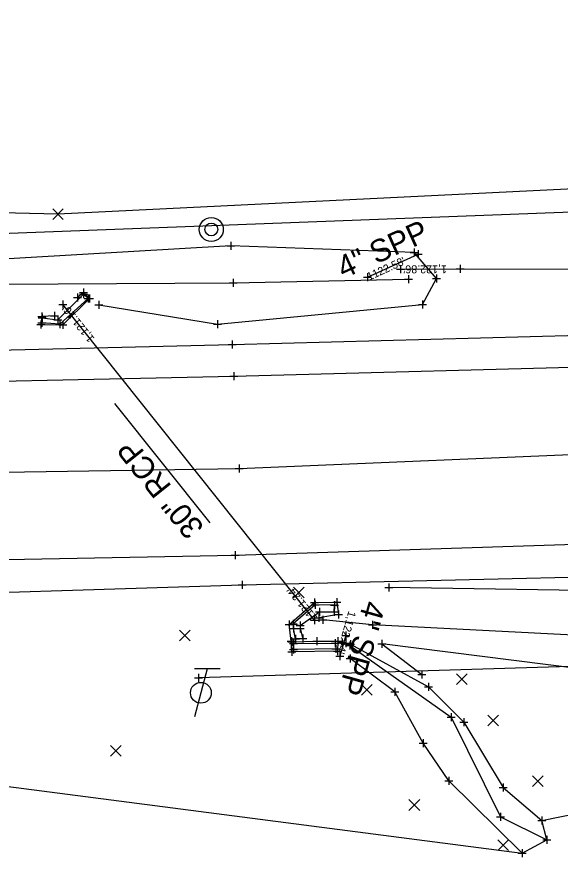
# Model space of a CAD drawing. Extents: x 2402028 to 2407435, y 498611 to 499105.
# Drawn here: x 2404008.8 to 2404076.7, y 498644.5 to 498749.5 of the extents above; entities that cross this region are included whole.
import ezdxf

# ---------------------------------------------------------------- set-up
doc = ezdxf.new("R2010")
doc.units = 0
for name, color, linetype in [('Default', 7, 'Continuous'), ('DR_X_Ditch', 7, 'Continuous'), ('DR_X_Headwall', 7, 'Continuous'), ('DR_X_Storm_Sewer', 7, 'Continuous'), ('DR_X_Text', 7, 'Continuous'), ('PV_X_COP', 7, 'Continuous'), ('PV_X_EOP', 7, 'Continuous'), ('PV_X_Shoulder', 7, 'Continuous'), ('RD_X_Wall', 7, 'Continuous'), ('RW_X_CL_1000_Distances', 7, 'Continuous'), ('RW_X_CL_100_Stations', 7, 'Continuous'), ('RW_X_CL_500_Bearings', 7, 'Continuous'), ('RW_X_CL_500_Distances', 7, 'Continuous'), ('RW_X_CL_500_Stations', 7, 'Continuous'), ('SC_Scratch1', 7, 'Continuous'), ('SV_X_Break_Lines', 7, 'Continuous'), ('SV_X_Terrain_Boundary', 7, 'Continuous'), ('UT_X_Telecom', 7, 'Continuous')]:
    doc.layers.add(name, color=color, linetype=linetype)

msp = doc.modelspace()

# ---------------------------------------------------------------- linework, layer by layer
at = {"layer": 'Default'}
for p, q in [((2404056.73, 498717.91), (2404056.73, 498717.91)), ((2404052.58, 498716.95), (2404052.58, 498716.95)), ((2404049.87, 498672.15), (2404049.87, 498672.15))]:
    msp.add_line(p, q, dxfattribs=at)
at = {"layer": 'DR_X_Ditch'}
for points in [[(2403115.12, 498695.09), (2403139.28, 498697.03), (2403188.69, 498698.47), (2403237.26, 498698.52), (2403287.58, 498700.04), (2403338.31, 498701.02), (2403388.05, 498703.88), (2403439.2, 498702.19), (2403487.16, 498703.92), (2403540.55, 498705.7), (2403586.78, 498706.71), (2403636.91, 498706.23), (2403686.46, 498707.34), (2403736.22, 498708.05), (2403785.8, 498709.01), (2403836.25, 498710.7), (2403885.81, 498712.33), (2403935.71, 498713.55), (2403984.74, 498715.92), (2404035.79, 498716.24), (2404057.73, 498716.67)], [(2404533.24, 498683.6), (2404485.13, 498682.32), (2404436.39, 498681.96), (2404386.54, 498679.04), (2404337.17, 498678.98), (2404287.56, 498677.96), (2404236.98, 498675.49), (2404187.96, 498674.52), (2404135.48, 498673.31), (2404086.4, 498671.8), (2404053.2, 498673.48), (2404047.02, 498674.14)], [(2404049.43, 498671.29), (2404049.9, 498671.22), (2404050.39, 498670.91), (2404063.05, 498661.97), (2404069.21, 498649.49), (2404075.01, 498646.62)]]:
    msp.add_lwpolyline(points, dxfattribs=at)
at = {"layer": 'DR_X_Headwall'}
msp.add_lwpolyline([(2404048.44, 498675.13), (2404048.49, 498675.97), (2404046.06, 498676), (2404043.3, 498673.64), (2404044.17, 498673.42), (2404046.58, 498675.13)], close=True, dxfattribs=at)
at = {"layer": 'DR_X_Storm_Sewer'}
for p, q in [((2404052.58, 498716.95), (2404058.92, 498719.82)), ((2404165.84, 498717.88), (2404056.73, 498717.91)), ((2404045.99, 498674.09), (2404014.53, 498713.5)), ((2404049.87, 498672.15), (2404049.14, 498669.58))]:
    msp.add_line(p, q, dxfattribs=at)
at = {"layer": 'DR_X_Text'}
msp.add_line((2404020.99, 498701.16), (2404032.89, 498686.25), dxfattribs=at)
at = {"layer": 'PV_X_COP'}
msp.add_lwpolyline([(2403985.57, 498692.23), (2404036.54, 498693.02), (2404085.82, 498695.1), (2404135.38, 498696.42), (2404186.49, 498697.31), (2404235.26, 498698.66), (2404284.95, 498699.47), (2404334.96, 498700.99), (2404383.89, 498702.2), (2404434.73, 498703.18), (2404484.39, 498704.35), (2404533.55, 498705.6)], dxfattribs=at)
at = {"layer": 'PV_X_EOP'}
for points in [[(2403338.61, 498686.54), (2403387.34, 498688.53), (2403437.74, 498689.31), (2403487.06, 498690.99), (2403539.21, 498692.01), (2403587.62, 498693.45), (2403637.16, 498694.45), (2403686.98, 498695.6), (2403736.54, 498696.76), (2403786.79, 498698.23), (2403836.48, 498699.49), (2403886.02, 498700.75), (2403935.9, 498702.14), (2403985.32, 498703.46), (2404035.9, 498704.57), (2404085.81, 498705.89), (2404135.13, 498707.56), (2404185.41, 498708.59), (2404200.68, 498708.71)], [(2403985.56, 498681.24), (2404036.04, 498682.2), (2404086.24, 498683.82), (2404136.5, 498684.82), (2404187.36, 498686.15), (2404235.32, 498687.11), (2404285.36, 498688.37), (2404336.4, 498689.7), (2404384.93, 498690.9), (2404435.67, 498692.09), (2404485.01, 498693.22), (2404533.25, 498694.59)]]:
    msp.add_lwpolyline(points, dxfattribs=at)
at = {"layer": 'PV_X_Shoulder'}
for p, q in [((2404035.7, 498708.5), (2404085.38, 498709.86)), ((2403985.28, 498707.32), (2404035.7, 498708.5))]:
    msp.add_line(p, q, dxfattribs=at)
msp.add_lwpolyline([(2403986.56, 498676.91), (2404036.95, 498678.51), (2404086.64, 498679.64), (2404136.45, 498680.88), (2404187.63, 498682.62), (2404236.08, 498683.33), (2404286.33, 498684.49), (2404336.81, 498686.17), (2404385.43, 498687.48), (2404436.29, 498688.5), (2404485.75, 498689.82), (2404533.69, 498691.17)], dxfattribs=at)
at = {"layer": 'RD_X_Wall'}
for points in [[(2404017.11, 498714.8), (2404017.7, 498714.26), (2404014.15, 498711.05), (2404011.91, 498711.23), (2404011.93, 498711.84), (2404013.9, 498711.62)], [(2404044.52, 498671.77), (2404043.6, 498671.73), (2404043.35, 498673.05), (2404044.16, 498673.04)], [(2404043.34, 498670.42), (2404043.34, 498671.16), (2404048.56, 498671.21), (2404048.64, 498670.51)]]:
    msp.add_lwpolyline(points, close=True, dxfattribs=at)
at = {"layer": 'RW_X_CL_1000_Distances'}
for p, q in [((2404032.58, 498668.01), (2404030.97, 498662.01)), ((2404034.18, 498668.01), (2404030.98, 498668.01))]:
    msp.add_line(p, q, dxfattribs=at)
msp.add_circle((2404031.78, 498665.01), 1.3, dxfattribs=at)
at = {"layer": 'RW_X_CL_100_Stations'}
for radius in [1.5, 0.8]:
    msp.add_circle((2404033.08, 498722.89), radius, dxfattribs=at)
at = {"layer": 'RW_X_CL_500_Bearings'}
for p, q in [((2404035, 498720.85), (2404036, 498720.85)), ((2404035.5, 498721.35), (2404035.5, 498720.35)), ((2404035.5, 498720.85), (2404035.5, 498720.85)), ((2404058.41, 498720.52), (2404058.41, 498719.52)), ((2404057.91, 498720.02), (2404058.91, 498720.02)), ((2404058.41, 498720.02), (2404058.41, 498720.02)), ((2404035.29, 498716.24), (2404036.29, 498716.24)), ((2404035.79, 498716.74), (2404035.79, 498715.74)), ((2404035.79, 498716.24), (2404035.79, 498716.24)), ((2404057.23, 498716.67), (2404058.23, 498716.67)), ((2404057.73, 498717.17), (2404057.73, 498716.17)), ((2404057.73, 498716.67), (2404057.73, 498716.67)), ((2404060.73, 498716.75), (2404061.73, 498716.75)), ((2404061.23, 498717.25), (2404061.23, 498716.25)), ((2404061.23, 498716.75), (2404061.23, 498716.75)), ((2404017.11, 498715.3), (2404017.11, 498714.3)), ((2404017.12, 498715.5), (2404017.12, 498714.5)), ((2404015.85, 498714.41), (2404016.85, 498714.41)), ((2404016.35, 498714.91), (2404016.35, 498713.91)), ((2404016.35, 498714.41), (2404016.35, 498714.41)), ((2404016.61, 498714.8), (2404017.61, 498714.8)), ((2404016.62, 498715), (2404017.62, 498715)), ((2404017.11, 498714.8), (2404017.11, 498714.8)), ((2404017.12, 498715), (2404017.12, 498715)), ((2404017.2, 498714.26), (2404018.2, 498714.26)), ((2404017.36, 498714.25), (2404018.36, 498714.25)), ((2404017.7, 498714.76), (2404017.7, 498713.76)), ((2404017.7, 498714.26), (2404017.7, 498714.26)), ((2404017.86, 498714.75), (2404017.86, 498713.75)), ((2404017.86, 498714.25), (2404017.86, 498714.25)), ((2404018.54, 498713.49), (2404019.54, 498713.49)), ((2404019.04, 498713.99), (2404019.04, 498712.99)), ((2404019.04, 498713.49), (2404019.04, 498713.49)), ((2404058.98, 498713.51), (2404059.98, 498713.51)), ((2404059.48, 498714.01), (2404059.48, 498713.01)), ((2404059.48, 498713.51), (2404059.48, 498713.51)), ((2404011.41, 498712.01), (2404012.41, 498712.01)), ((2404011.91, 498712.51), (2404011.91, 498711.51)), ((2404011.91, 498712.01), (2404011.91, 498712.01)), ((2404011.93, 498712.34), (2404011.93, 498711.34)), ((2404012.98, 498712.1), (2404013.98, 498712.1)), ((2404013.48, 498712.6), (2404013.48, 498711.6)), ((2404013.48, 498712.1), (2404013.48, 498712.1)), ((2404013.9, 498712.12), (2404013.9, 498711.12)), ((2404011.27, 498711.01), (2404012.27, 498711.01)), ((2404011.41, 498711.23), (2404012.41, 498711.23)), ((2404011.43, 498711.84), (2404012.43, 498711.84)), ((2404011.77, 498711.51), (2404011.77, 498710.51)), ((2404011.77, 498711.01), (2404011.77, 498711.01)), ((2404011.91, 498711.73), (2404011.91, 498710.73)), ((2404011.91, 498711.23), (2404011.91, 498711.23)), ((2404011.93, 498711.84), (2404011.93, 498711.84)), ((2404013.4, 498711.62), (2404014.4, 498711.62)), ((2404013.65, 498711.05), (2404014.65, 498711.05)), ((2404013.9, 498711.62), (2404013.9, 498711.62)), ((2404014.03, 498710.96), (2404015.03, 498710.96)), ((2404014.15, 498711.55), (2404014.15, 498710.55)), ((2404014.15, 498711.05), (2404014.15, 498711.05)), ((2404014.53, 498711.46), (2404014.53, 498710.46)), ((2404014.53, 498710.96), (2404014.53, 498710.96)), ((2404033.34, 498711.06), (2404034.34, 498711.06)), ((2404033.84, 498711.56), (2404033.84, 498710.56)), ((2404033.84, 498711.06), (2404033.84, 498711.06)), ((2404035.7, 498709), (2404035.7, 498708)), ((2404035.2, 498708.5), (2404036.2, 498708.5)), ((2404035.7, 498708.5), (2404035.7, 498708.5)), ((2404035.9, 498705.07), (2404035.9, 498704.07)), ((2404035.4, 498704.57), (2404036.4, 498704.57)), ((2404035.9, 498704.57), (2404035.9, 498704.57)), ((2404036.54, 498693.52), (2404036.54, 498692.52)), ((2404036.04, 498693.02), (2404037.04, 498693.02)), ((2404036.54, 498693.02), (2404036.54, 498693.02)), ((2404036.04, 498682.7), (2404036.04, 498681.7)), ((2404035.54, 498682.2), (2404036.54, 498682.2)), ((2404036.04, 498682.2), (2404036.04, 498682.2)), ((2404036.45, 498678.51), (2404037.45, 498678.51)), ((2404036.95, 498679.01), (2404036.95, 498678.01)), ((2404036.95, 498678.51), (2404036.95, 498678.51)), ((2404055.25, 498678.64), (2404055.25, 498677.64)), ((2404054.75, 498678.14), (2404055.75, 498678.14)), ((2404055.25, 498678.14), (2404055.25, 498678.14)), ((2404045.97, 498676.77), (2404045.97, 498675.77)), ((2404046.06, 498676.5), (2404046.06, 498675.5)), ((2404048.26, 498676.34), (2404049.26, 498676.34)), ((2404048.49, 498676.47), (2404048.49, 498675.47)), ((2404048.76, 498676.84), (2404048.76, 498675.84)), ((2404048.76, 498676.34), (2404048.76, 498676.34)), ((2404045.47, 498676.27), (2404046.47, 498676.27)), ((2404045.56, 498676), (2404046.56, 498676)), ((2404045.97, 498676.27), (2404045.97, 498676.27)), ((2404046.06, 498676), (2404046.06, 498676)), ((2404046.58, 498675.63), (2404046.58, 498674.63)), ((2404047.99, 498675.97), (2404048.99, 498675.97)), ((2404048.44, 498675.63), (2404048.44, 498674.63)), ((2404048.49, 498675.97), (2404048.49, 498675.97)), ((2404048.97, 498675.28), (2404048.97, 498674.28)), ((2404046.01, 498674.37), (2404047.01, 498674.37)), ((2404046.08, 498675.13), (2404047.08, 498675.13)), ((2404046.51, 498674.87), (2404046.51, 498673.87)), ((2404046.51, 498674.37), (2404046.51, 498674.37)), ((2404046.58, 498675.13), (2404046.58, 498675.13)), ((2404047.02, 498674.64), (2404047.02, 498673.64)), ((2404047.94, 498675.13), (2404048.94, 498675.13)), ((2404048.44, 498675.13), (2404048.44, 498675.13)), ((2404048.47, 498674.78), (2404049.47, 498674.78)), ((2404048.97, 498674.78), (2404048.97, 498674.78)), ((2404042.29, 498673.54), (2404043.29, 498673.54)), ((2404042.79, 498674.04), (2404042.79, 498673.04)), ((2404042.79, 498673.54), (2404042.79, 498673.54)), ((2404042.8, 498673.64), (2404043.8, 498673.64)), ((2404043.3, 498674.14), (2404043.3, 498673.14)), ((2404043.3, 498673.64), (2404043.3, 498673.64)), ((2404043.35, 498673.55), (2404043.35, 498672.55)), ((2404043.67, 498673.42), (2404044.67, 498673.42)), ((2404044.16, 498673.54), (2404044.16, 498672.54)), ((2404044.17, 498673.92), (2404044.17, 498672.92)), ((2404044.17, 498673.42), (2404044.17, 498673.42)), ((2404046.52, 498674.14), (2404047.52, 498674.14)), ((2404047.02, 498674.14), (2404047.02, 498674.14)), ((2404052.7, 498673.48), (2404053.7, 498673.48)), ((2404053.2, 498673.98), (2404053.2, 498672.98)), ((2404053.2, 498673.48), (2404053.2, 498673.48)), ((2404042.85, 498673.05), (2404043.85, 498673.05)), ((2404043.35, 498673.05), (2404043.35, 498673.05)), ((2404043.6, 498672.23), (2404043.6, 498671.23)), ((2404043.66, 498673.04), (2404044.66, 498673.04)), ((2404044.16, 498673.04), (2404044.16, 498673.04)), ((2404044.52, 498672.27), (2404044.52, 498671.27)), ((2404042.57, 498671.45), (2404043.57, 498671.45)), ((2404042.64, 498671.38), (2404043.64, 498671.38)), ((2404042.84, 498671.16), (2404043.84, 498671.16)), ((2404043.07, 498671.95), (2404043.07, 498670.95)), ((2404043.07, 498671.45), (2404043.07, 498671.45)), ((2404043.1, 498671.73), (2404044.1, 498671.73)), ((2404043.14, 498671.88), (2404043.14, 498670.88)), ((2404043.14, 498671.38), (2404043.14, 498671.38)), ((2404043.34, 498671.66), (2404043.34, 498670.66)), ((2404043.34, 498671.16), (2404043.34, 498671.16)), ((2404043.6, 498671.73), (2404043.6, 498671.73)), ((2404044.02, 498671.77), (2404045.02, 498671.77)), ((2404044.52, 498671.77), (2404044.52, 498671.77)), ((2404045.77, 498671.46), (2404046.77, 498671.46)), ((2404046.27, 498671.96), (2404046.27, 498670.96)), ((2404046.27, 498671.46), (2404046.27, 498671.46)), ((2404048.06, 498671.21), (2404049.06, 498671.21)), ((2404048.38, 498671.47), (2404049.38, 498671.47)), ((2404048.56, 498671.71), (2404048.56, 498670.71)), ((2404048.56, 498671.21), (2404048.56, 498671.21)), ((2404048.88, 498671.97), (2404048.88, 498670.97)), ((2404048.88, 498671.47), (2404048.88, 498671.47)), ((2404048.93, 498671.29), (2404049.93, 498671.29)), ((2404049.4, 498671.22), (2404050.4, 498671.22)), ((2404049.43, 498671.79), (2404049.43, 498670.79)), ((2404049.43, 498671.29), (2404049.43, 498671.29)), ((2404049.9, 498671.72), (2404049.9, 498670.72)), ((2404049.9, 498671.22), (2404049.9, 498671.22)), ((2404049.96, 498671.09), (2404050.96, 498671.09)), ((2404050.39, 498671.41), (2404050.39, 498670.41)), ((2404050.46, 498671.59), (2404050.46, 498670.59)), ((2404050.46, 498671.09), (2404050.46, 498671.09)), ((2404053.9, 498671.14), (2404054.9, 498671.14)), ((2404054.4, 498671.64), (2404054.4, 498670.64)), ((2404054.4, 498671.14), (2404054.4, 498671.14)), ((2404042.64, 498670.12), (2404043.64, 498670.12)), ((2404042.84, 498670.42), (2404043.84, 498670.42)), ((2404043.14, 498670.62), (2404043.14, 498669.62)), ((2404043.14, 498670.12), (2404043.14, 498670.12)), ((2404043.34, 498670.92), (2404043.34, 498669.92)), ((2404043.34, 498670.42), (2404043.34, 498670.42)), ((2404048.14, 498670.51), (2404049.14, 498670.51)), ((2404048.33, 498670.2), (2404049.33, 498670.2)), ((2404048.64, 498671.01), (2404048.64, 498670.01)), ((2404048.64, 498670.51), (2404048.64, 498670.51)), ((2404048.83, 498670.7), (2404048.83, 498669.7)), ((2404048.83, 498670.2), (2404048.83, 498670.2)), ((2404049.89, 498670.91), (2404050.89, 498670.91)), ((2404050.39, 498670.91), (2404050.39, 498670.91)), ((2404049.93, 498669.29), (2404050.93, 498669.29)), ((2404050.43, 498669.79), (2404050.43, 498668.79)), ((2404050.43, 498669.29), (2404050.43, 498669.29)), ((2404030.96, 498666.86), (2404031.96, 498666.86)), ((2404031.46, 498667.36), (2404031.46, 498666.36)), ((2404031.46, 498666.86), (2404031.46, 498666.86)), ((2404058.89, 498667.3), (2404059.89, 498667.3)), ((2404059.39, 498667.8), (2404059.39, 498666.8)), ((2404059.39, 498667.3), (2404059.39, 498667.3)), ((2404060.22, 498666.25), (2404060.22, 498665.25)), ((2404055.51, 498665.12), (2404056.51, 498665.12)), ((2404056.01, 498665.62), (2404056.01, 498664.62)), ((2404056.01, 498665.12), (2404056.01, 498665.12)), ((2404059.72, 498665.75), (2404060.72, 498665.75)), ((2404060.22, 498665.75), (2404060.22, 498665.75)), ((2404062.55, 498661.97), (2404063.55, 498661.97)), ((2404063.05, 498662.47), (2404063.05, 498661.47)), ((2404063.05, 498661.97), (2404063.05, 498661.97)), ((2404064.61, 498661.85), (2404064.61, 498660.85)), ((2404064.11, 498661.35), (2404065.11, 498661.35)), ((2404064.61, 498661.35), (2404064.61, 498661.35)), ((2404059.06, 498658.73), (2404060.06, 498658.73)), ((2404059.56, 498659.23), (2404059.56, 498658.23)), ((2404059.56, 498658.73), (2404059.56, 498658.73)), ((2404062.75, 498654.5), (2404062.75, 498653.5)), ((2404062.25, 498654), (2404063.25, 498654)), ((2404062.75, 498654), (2404062.75, 498654)), ((2404069.55, 498653.66), (2404069.55, 498652.66)), ((2404069.05, 498653.16), (2404070.05, 498653.16)), ((2404069.55, 498653.16), (2404069.55, 498653.16)), ((2404068.71, 498649.49), (2404069.71, 498649.49)), ((2404069.21, 498649.99), (2404069.21, 498648.99)), ((2404069.21, 498649.49), (2404069.21, 498649.49)), ((2404073.86, 498649.06), (2404074.86, 498649.06)), ((2404074.36, 498649.56), (2404074.36, 498648.56)), ((2404074.36, 498649.06), (2404074.36, 498649.06)), ((2404075.01, 498647.12), (2404075.01, 498646.12)), ((2404074.51, 498646.62), (2404075.51, 498646.62)), ((2404075.01, 498646.62), (2404075.01, 498646.62)), ((2404071.43, 498644.97), (2404072.43, 498644.97)), ((2404071.93, 498645.47), (2404071.93, 498644.47)), ((2404071.93, 498644.97), (2404071.93, 498644.97))]:
    msp.add_line(p, q, dxfattribs=at)
at = {"layer": 'RW_X_CL_500_Distances'}
for p, q in [((2404058.42, 498719.82), (2404059.42, 498719.82)), ((2404058.92, 498720.32), (2404058.92, 498719.32)), ((2404058.92, 498719.82), (2404058.92, 498719.82)), ((2404056.73, 498718.41), (2404056.73, 498717.41)), ((2404064.17, 498718.47), (2404064.17, 498717.47)), ((2404052.58, 498717.45), (2404052.58, 498716.45)), ((2404056.23, 498717.91), (2404057.23, 498717.91)), ((2404056.73, 498717.91), (2404056.73, 498717.91)), ((2404063.67, 498717.97), (2404064.67, 498717.97)), ((2404064.17, 498717.97), (2404064.17, 498717.97)), ((2404052.08, 498716.95), (2404053.08, 498716.95)), ((2404052.58, 498716.95), (2404052.58, 498716.95)), ((2404014.03, 498713.5), (2404015.03, 498713.5)), ((2404014.53, 498714), (2404014.53, 498713)), ((2404014.53, 498713.5), (2404014.53, 498713.5)), ((2404045.99, 498674.59), (2404045.99, 498673.59)), ((2404045.49, 498674.09), (2404046.49, 498674.09)), ((2404045.99, 498674.09), (2404045.99, 498674.09)), ((2404049.37, 498672.15), (2404050.37, 498672.15)), ((2404049.87, 498672.65), (2404049.87, 498671.65)), ((2404049.87, 498672.15), (2404049.87, 498672.15)), ((2404049.14, 498670.08), (2404049.14, 498669.08)), ((2404048.64, 498669.58), (2404049.64, 498669.58)), ((2404049.14, 498669.58), (2404049.14, 498669.58))]:
    msp.add_line(p, q, dxfattribs=at)
at = {"layer": 'RW_X_CL_500_Stations'}
for p, q in [((2404013.26, 498724.13), (2404014.59, 498725.47)), ((2404013.26, 498725.47), (2404014.59, 498724.13)), ((2404043.35, 498676.88), (2404044.68, 498678.21)), ((2404043.35, 498678.21), (2404044.68, 498676.88)), ((2404029.11, 498671.5), (2404030.44, 498672.83)), ((2404029.11, 498672.83), (2404030.44, 498671.5)), ((2404063.7, 498666.04), (2404065.04, 498667.38)), ((2404063.7, 498667.38), (2404065.04, 498666.04)), ((2404051.86, 498664.71), (2404053.19, 498666.05)), ((2404051.86, 498666.05), (2404053.19, 498664.71)), ((2404067.63, 498660.88), (2404068.97, 498662.21)), ((2404067.63, 498662.21), (2404068.97, 498660.88)), ((2404020.48, 498657.07), (2404021.81, 498658.41)), ((2404020.48, 498658.41), (2404021.81, 498657.07)), ((2404073.21, 498653.29), (2404074.54, 498654.63)), ((2404073.21, 498654.63), (2404074.54, 498653.29)), ((2404057.77, 498650.32), (2404059.11, 498651.66)), ((2404057.77, 498651.66), (2404059.11, 498650.32)), ((2404068.86, 498645.3), (2404070.2, 498646.63)), ((2404068.86, 498646.63), (2404070.2, 498645.3))]:
    msp.add_line(p, q, dxfattribs=at)
at = {"layer": 'SV_X_Break_Lines'}
for points in [[(2404019.04, 498713.49), (2404033.84, 498711.06), (2404059.48, 498713.51), (2404061.23, 498716.75), (2404058.41, 498720.02), (2404035.5, 498720.85), (2403984.19, 498717.86), (2403935.32, 498717.7), (2403885.41, 498717.04), (2403835.4, 498717.35), (2403785.05, 498718.48), (2403735.06, 498717.48), (2403685.61, 498714.83), (2403635.75, 498713.46), (2403587.21, 498711.88)], [(2404013.48, 498712.1), (2404011.91, 498712.01), (2404011.77, 498711.01), (2404014.53, 498710.96), (2404017.86, 498714.25), (2404017.12, 498715), (2404016.35, 498714.41)], [(2404534.29, 498688.61), (2404486.42, 498687.58), (2404437.42, 498686.5), (2404385.81, 498685.86), (2404336.79, 498684.01), (2404286.16, 498682.85), (2404233.91, 498680.95), (2404188.17, 498680.27), (2404137.24, 498679.18), (2404087.21, 498677.64), (2404055.25, 498678.14)], [(2404534.06, 498678.67), (2404487.14, 498679.19), (2404435.91, 498680.7), (2404386.18, 498676.8), (2404335.53, 498673.1), (2404285.8, 498675.24), (2404235.32, 498670.62), (2404187.68, 498672.55), (2404137.13, 498671.73), (2404087.36, 498666.97), (2404054.4, 498671.14), (2404059.39, 498667.3)], [(2404043.14, 498671.38), (2404046.27, 498671.46), (2404048.88, 498671.47), (2404048.83, 498670.2), (2404043.14, 498670.12), (2404043.07, 498671.45), (2404042.79, 498673.54), (2404045.97, 498676.27), (2404048.76, 498676.34), (2404048.97, 498674.78), (2404046.51, 498674.37)], [(2404050.46, 498671.09), (2404060.22, 498665.75), (2404064.61, 498661.35), (2404069.55, 498653.16), (2404074.36, 498649.06)], [(2404071.93, 498644.97), (2404062.75, 498654), (2404059.56, 498658.73), (2404056.01, 498665.12), (2404050.43, 498669.29)]]:
    msp.add_lwpolyline(points, dxfattribs=at)
at = {"layer": 'SV_X_Terrain_Boundary'}
for points in [[(2404243.83, 498747.15), (2404234.24, 498749.33), (2404224.02, 498749.46), (2404209.73, 498748.79), (2404134.41, 498728.23), (2404084.34, 498728.27), (2404013.92, 498724.8), (2403983.78, 498725.5)], [(2403985.55, 498656.18), (2404071.93, 498644.97), (2404075.01, 498646.62), (2404074.36, 498649.06), (2404127.78, 498659.91), (2404178.06, 498661.8), (2404232.73, 498665.07), (2404291.58, 498664.1)]]:
    msp.add_lwpolyline(points, dxfattribs=at)
at = {"layer": 'UT_X_Telecom'}
for points in [[(2404085.8, 498725.33), (2403922.2, 498719.12)], [(2404196.79, 498671.91), (2404031.46, 498666.86)]]:
    msp.add_lwpolyline(points, dxfattribs=at)

# ---------------------------------------------------------------- texts
at = {"layer": 'DR_X_Text'}
for s, rotation, p in [('4" SPP', 24.3834, (2404049.6, 498716.69)), ('30" RCP', 128.6032, (2404032.29, 498685.69)), ('4" SPP', 254.2251, (2404052.17, 498676.66))]:
    msp.add_text(s, height=2.8, rotation=rotation, dxfattribs=at).set_placement(p)
at = {"layer": 'SC_Scratch1'}
for s, rotation, p in [("1122.58'", 24.3834, (2404052.79, 498716.49)), ("1,122.86'", 179.9879, (2404062.52, 498718.41)), ("1,121.16'", 128.6032, (2404018.54, 498709.28)), ("1121.24'", 128.6032, (2404046.38, 498674.41)), ("1,122.44'", 254.2251, (2404050.23, 498675.29))]:
    msp.add_text(s, height=1, rotation=rotation, dxfattribs=at).set_placement(p)

doc.saveas('drawing.dxf')
